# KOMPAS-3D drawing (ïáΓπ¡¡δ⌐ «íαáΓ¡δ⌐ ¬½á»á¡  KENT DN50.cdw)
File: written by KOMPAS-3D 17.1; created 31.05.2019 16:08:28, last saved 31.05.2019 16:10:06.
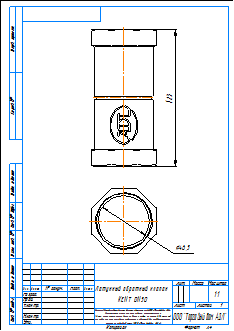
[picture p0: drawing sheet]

Sheet 1: A4, portrait

Title block, sheet 1: name: Латунный обратный клапан / KENT DN50; material: Внимание! Данный продукт является объектом авторского права ООО «Торговый Дом АДЛ». / Запрещается изменение, копирование, распространение / (в том числе путем копирования на другие сайты и ресурсы в Интернете) / или любое иное использование информации и объектов без предварительного / согласия правообладателя (ООО «Торговый Дом АДЛ»).; sheets: 1; organisation: ООО "Торговый дом АДЛ"; sheet format: A4

Views: Вид 1, Проекционный вид 2
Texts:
  user
Dimensions and other numbers on the sheet: 46,5; 123; 1:1; 1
